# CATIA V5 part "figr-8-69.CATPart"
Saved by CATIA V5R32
Part number: Part1
Bounding box of the stored display mesh (mm): x -75 to 75, y -65.851 to 65.851, z 0 to 50
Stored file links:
  D:\PROJECTS\Project 2022\CATIA V5 6R 2022\Resources\Part Files\c08_catia_v5_6r2022_prt\figr-8-69.CATPart
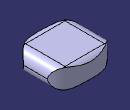
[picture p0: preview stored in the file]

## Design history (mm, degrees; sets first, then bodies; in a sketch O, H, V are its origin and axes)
Body1 (main body)
  Sketch1 on xy-plane, origin (0, 0, 0), H (1, 0, 0), V (0, 1, 0)
    line L1 (-75, 75) -> (75, 75)
    line L2 (75, 75) -> (75, -75)
    line L3 (75, -75) -> (-75, -75)
    line L4 (-75, -75) -> (-75, 75)
    axis line L5 (75, -75) -> (-75, 75)
    length L3 = 150
    length L2 = 150
    horizontal: L1 H, L3 H
    vertical: L2 V, L4 V
    midpoint: O L5
  Pad1: profile Sketch1, direction (0, 0, 1), length 50
  Fillet1: radius 25, on face of Pad1 (x6)
  Body2
    Sketch2 on xy-plane, origin (0, 0, 0), H (1, 0, 0), V (0, 1, 0)
      ellipse A1 centre (0, 0) semi-axes 84.7617, 65.8627 rotation 0
      point P1 (84.7617, 0)
      point P2 (0, 65.8627)
      coincidence: P1 H, P2 V, A1 P1, A1 P2
    Pad2: profile Sketch2, direction (0, 0, 1), length 50
  Intersect1: tool Body2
